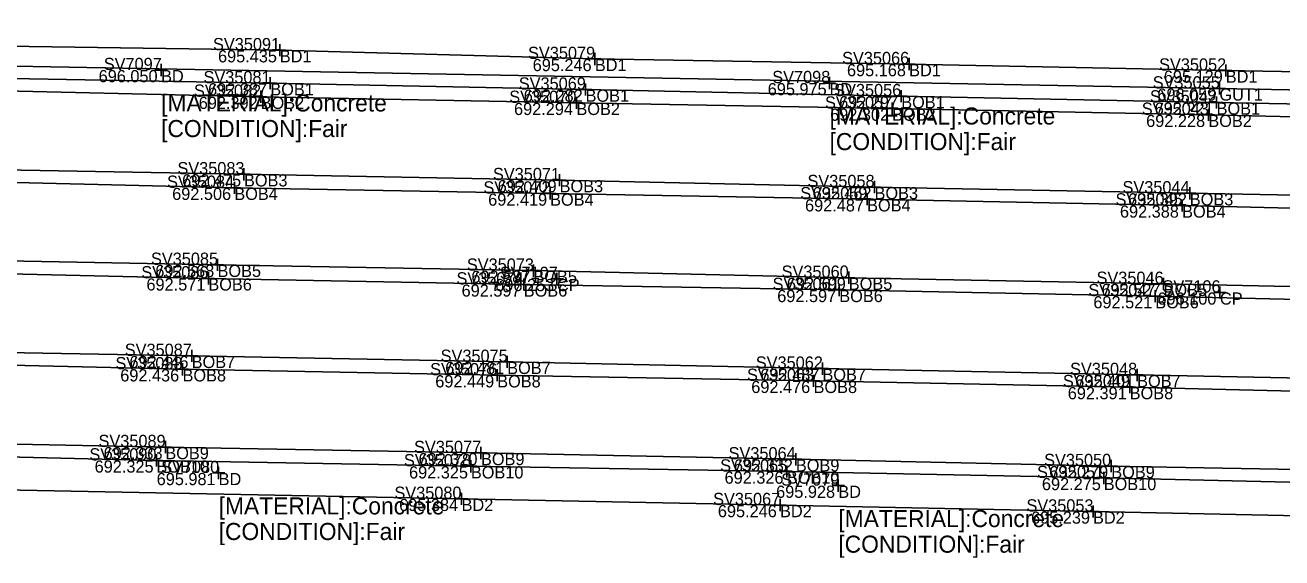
# Model space of a CAD drawing. Extents: x 1660019 to 1662995, y 619975 to 620342.
# Drawn here: x 1661348 to 1661451.1, y 620208.1 to 620251.8 of the extents above; entities that cross this region are included whole.
import ezdxf

# ---------------------------------------------------------------- set-up
doc = ezdxf.new("R2010")
doc.units = 0
for name, color, linetype in [('BR_X_Rail_Object', 7, 'Continuous'), ('BR_X_SV_Bottom_of_Beam', 7, 'Continuous'), ('BR_X_SV_Bottom_of_Beam_Text', 7, 'Continuous'), ('BR_X_SV_Deck_Top', 7, 'Continuous'), ('BR_X_SV_Deck_Top_Text', 7, 'Continuous'), ('PV_X_Curb', 7, 'Continuous'), ('RD_P_GR_Lt', 7, 'Continuous'), ('RD_X_GR_Bar', 7, 'Continuous'), ('RD_X_Wall', 7, 'Continuous'), ('SV_X_Text', 7, 'Continuous')]:
    doc.layers.add(name, color=color, linetype=linetype)

msp = doc.modelspace()

# ---------------------------------------------------------------- linework, layer by layer
at = {"layer": 'BR_X_SV_Bottom_of_Beam'}
for points in [[(1661523.4, 620243.85), (1661497.42, 620244.38), (1661471.69, 620244.95), (1661445.77, 620245.45), (1661419.9, 620245.97), (1661394.01, 620246.51), (1661368.15, 620247.03), (1661342.29, 620247.49), (1661316.31, 620248.04), (1661290.56, 620248.6), (1661264.65, 620249.03), (1661238.6, 620249.58)], [(1661517.58, 620243.01), (1661496.9, 620243.44), (1661470.92, 620243.84), (1661445.09, 620244.44), (1661419.15, 620244.95), (1661393.26, 620245.42), (1661367.36, 620245.92), (1661341.63, 620246.52), (1661315.65, 620247.11), (1661289.75, 620247.52), (1661264.38, 620248.32), (1661238.2, 620248.61)], [(1661521.26, 620236.36), (1661495.33, 620236.96), (1661469.49, 620237.51), (1661443.57, 620238), (1661417.71, 620238.51), (1661391.88, 620239.08), (1661365.99, 620239.56), (1661340.12, 620240.03), (1661314.2, 620240.59), (1661288.35, 620241.15), (1661262.48, 620241.61), (1661236.62, 620242.15)], [(1661520.6, 620235.45), (1661494.63, 620235.97), (1661468.71, 620236.38), (1661442.94, 620237), (1661417.1, 620237.51), (1661391.1, 620237.98), (1661365.2, 620238.45), (1661339.37, 620239.07), (1661313.5, 620239.59), (1661287.59, 620239.99), (1661261.72, 620240.63), (1661235.91, 620241.14)], [(1661519.08, 620228.95), (1661493.23, 620229.44), (1661467.37, 620230.03), (1661441.42, 620230.57), (1661415.6, 620231.07), (1661389.73, 620231.65), (1661363.82, 620232.13), (1661337.82, 620232.61), (1661311.99, 620233.08), (1661286.18, 620233.72), (1661260.33, 620234.13), (1661234.38, 620234.66)], [(1661518.51, 620227.98), (1661492.53, 620228.47), (1661466.56, 620228.95), (1661440.74, 620229.56), (1661414.82, 620230.07), (1661388.94, 620230.52), (1661363.07, 620231.02), (1661337.3, 620231.61), (1661311.53, 620232.16), (1661285.45, 620232.59), (1661259.59, 620233.14), (1661233.67, 620233.67)], [(1661516.94, 620221.49), (1661491.08, 620222.02), (1661465.19, 620222.58), (1661439.25, 620223.09), (1661413.44, 620223.61), (1661387.58, 620224.17), (1661361.7, 620224.66), (1661335.74, 620225.13), (1661309.88, 620225.69), (1661284.01, 620226.24), (1661258.16, 620226.7), (1661232.1, 620227.23)], [(1661516.25, 620220.54), (1661490.62, 620220.91), (1661464.53, 620221.45), (1661438.64, 620222.1), (1661412.71, 620222.61), (1661386.76, 620223.07), (1661360.95, 620223.56), (1661335.05, 620224.18), (1661309.21, 620224.72), (1661283.27, 620225.13), (1661257.54, 620225.69), (1661231.6, 620226.26)], [(1661514.76, 620214.06), (1661488.91, 620214.55), (1661463.02, 620215.15), (1661437.13, 620215.62), (1661411.26, 620216.17), (1661385.43, 620216.69), (1661359.54, 620217.18), (1661333.6, 620217.68), (1661307.75, 620218.18), (1661281.89, 620218.77), (1661255.86, 620219.28), (1661229.67, 620219.8)], [(1661514.07, 620213.08), (1661488.21, 620213.6), (1661462.26, 620214.04), (1661436.51, 620214.64), (1661410.52, 620215.17), (1661384.6, 620215.6), (1661358.81, 620216.08), (1661332.97, 620216.7), (1661307.11, 620217.25), (1661281.1, 620217.69), (1661255.32, 620218.27), (1661229.46, 620218.85)]]:
    msp.add_lwpolyline(points, dxfattribs=at)
at = {"layer": 'BR_X_SV_Deck_Top'}
for points in [[(1661524.15, 620246.52), (1661498.29, 620247.07), (1661472.43, 620247.6), (1661446.52, 620248.07), (1661420.55, 620248.6), (1661394.77, 620249.02), (1661368.93, 620249.74), (1661342.74, 620250.12), (1661316.87, 620250.71), (1661291.25, 620251.01), (1661265.13, 620251.8)], [(1661513.53, 620210.29), (1661487.66, 620211.1), (1661461.66, 620211.35), (1661435.63, 620211.89), (1661409.96, 620212.42), (1661383.84, 620212.93), (1661332.3, 620213.95), (1661306.25, 620214.44), (1661280.43, 620214.97), (1661254.73, 620215.77)]]:
    msp.add_lwpolyline(points, dxfattribs=at)
at = {"layer": 'PV_X_Curb'}
msp.add_lwpolyline([(1661523.34, 620245.12), (1661471.57, 620246.11), (1661446, 620246.6), (1661316.22, 620249.01), (1661290.79, 620249.44), (1661264.95, 620250.25), (1661238.71, 620250.79)], dxfattribs=at)
at = {"layer": 'RD_P_GR_Lt'}
for p, q in [((1661368.43, 620249.74), (1661369.43, 620249.74)), ((1661368.93, 620250.24), (1661368.93, 620249.24)), ((1661368.93, 620249.74), (1661368.93, 620249.74)), ((1661394.77, 620249.52), (1661394.77, 620248.52)), ((1661359.19, 620248.61), (1661359.19, 620247.61)), ((1661394.27, 620249.02), (1661395.27, 620249.02)), ((1661394.77, 620249.02), (1661394.77, 620249.02)), ((1661420.05, 620248.6), (1661421.05, 620248.6)), ((1661420.55, 620249.1), (1661420.55, 620248.1)), ((1661420.55, 620248.6), (1661420.55, 620248.6)), ((1661446.52, 620248.57), (1661446.52, 620247.57)), ((1661358.69, 620248.11), (1661359.69, 620248.11)), ((1661359.19, 620248.11), (1661359.19, 620248.11)), ((1661368.15, 620247.53), (1661368.15, 620246.53)), ((1661414.02, 620247.54), (1661414.02, 620246.54)), ((1661446.02, 620248.07), (1661447.02, 620248.07)), ((1661446.52, 620248.07), (1661446.52, 620248.07)), ((1661367.36, 620246.42), (1661367.36, 620245.42)), ((1661367.65, 620247.03), (1661368.65, 620247.03)), ((1661368.15, 620247.03), (1661368.15, 620247.03)), ((1661393.51, 620246.51), (1661394.51, 620246.51)), ((1661394.01, 620247.01), (1661394.01, 620246.01)), ((1661394.01, 620246.51), (1661394.01, 620246.51)), ((1661413.52, 620247.04), (1661414.52, 620247.04)), ((1661414.02, 620247.04), (1661414.02, 620247.04)), ((1661419.9, 620246.47), (1661419.9, 620245.47)), ((1661445.5, 620246.6), (1661446.5, 620246.6)), ((1661446, 620247.1), (1661446, 620246.1)), ((1661446, 620246.6), (1661446, 620246.6)), ((1661366.86, 620245.92), (1661367.86, 620245.92)), ((1661367.36, 620245.92), (1661367.36, 620245.92)), ((1661392.76, 620245.42), (1661393.76, 620245.42)), ((1661393.26, 620245.92), (1661393.26, 620244.92)), ((1661393.26, 620245.42), (1661393.26, 620245.42)), ((1661419.15, 620245.45), (1661419.15, 620244.45)), ((1661419.4, 620245.97), (1661420.4, 620245.97)), ((1661419.9, 620245.97), (1661419.9, 620245.97)), ((1661445.27, 620245.45), (1661446.27, 620245.45)), ((1661445.77, 620245.95), (1661445.77, 620244.95)), ((1661445.77, 620245.45), (1661445.77, 620245.45)), ((1661418.65, 620244.95), (1661419.65, 620244.95)), ((1661419.15, 620244.95), (1661419.15, 620244.95)), ((1661444.59, 620244.44), (1661445.59, 620244.44)), ((1661445.09, 620244.94), (1661445.09, 620243.94)), ((1661445.09, 620244.44), (1661445.09, 620244.44)), ((1661365.49, 620239.56), (1661366.49, 620239.56)), ((1661365.99, 620240.06), (1661365.99, 620239.06)), ((1661365.99, 620239.56), (1661365.99, 620239.56)), ((1661391.88, 620239.58), (1661391.88, 620238.58)), ((1661364.7, 620238.45), (1661365.7, 620238.45)), ((1661365.2, 620238.95), (1661365.2, 620237.95)), ((1661365.2, 620238.45), (1661365.2, 620238.45)), ((1661391.1, 620238.48), (1661391.1, 620237.48)), ((1661391.38, 620239.08), (1661392.38, 620239.08)), ((1661391.88, 620239.08), (1661391.88, 620239.08)), ((1661417.21, 620238.51), (1661418.21, 620238.51)), ((1661417.71, 620239.01), (1661417.71, 620238.01)), ((1661417.71, 620238.51), (1661417.71, 620238.51)), ((1661443.57, 620238.5), (1661443.57, 620237.5)), ((1661390.6, 620237.98), (1661391.6, 620237.98)), ((1661391.1, 620237.98), (1661391.1, 620237.98)), ((1661416.6, 620237.51), (1661417.6, 620237.51)), ((1661417.1, 620238.01), (1661417.1, 620237.01)), ((1661417.1, 620237.51), (1661417.1, 620237.51)), ((1661442.94, 620237.5), (1661442.94, 620236.5)), ((1661443.07, 620238), (1661444.07, 620238)), ((1661443.57, 620238), (1661443.57, 620238)), ((1661442.44, 620237), (1661443.44, 620237)), ((1661442.94, 620237), (1661442.94, 620237)), ((1661363.32, 620232.13), (1661364.32, 620232.13)), ((1661363.82, 620232.63), (1661363.82, 620231.63)), ((1661363.82, 620232.13), (1661363.82, 620232.13)), ((1661389.73, 620232.15), (1661389.73, 620231.15)), ((1661362.57, 620231.02), (1661363.57, 620231.02)), ((1661363.07, 620231.52), (1661363.07, 620230.52)), ((1661363.07, 620231.02), (1661363.07, 620231.02)), ((1661388.94, 620231.02), (1661388.94, 620230.02)), ((1661389.23, 620231.65), (1661390.23, 620231.65)), ((1661389.73, 620231.65), (1661389.73, 620231.65)), ((1661391.16, 620230.97), (1661392.16, 620230.97)), ((1661391.66, 620231.47), (1661391.66, 620230.47)), ((1661391.66, 620230.97), (1661391.66, 620230.97)), ((1661415.1, 620231.07), (1661416.1, 620231.07)), ((1661415.6, 620231.57), (1661415.6, 620230.57)), ((1661415.6, 620231.07), (1661415.6, 620231.07)), ((1661441.42, 620231.07), (1661441.42, 620230.07)), ((1661388.44, 620230.52), (1661389.44, 620230.52)), ((1661388.94, 620230.52), (1661388.94, 620230.52)), ((1661414.32, 620230.07), (1661415.32, 620230.07)), ((1661414.82, 620230.57), (1661414.82, 620229.57)), ((1661414.82, 620230.07), (1661414.82, 620230.07)), ((1661440.74, 620230.06), (1661440.74, 620229.06)), ((1661440.92, 620230.57), (1661441.92, 620230.57)), ((1661441.42, 620230.57), (1661441.42, 620230.57)), ((1661446.04, 620230.36), (1661446.04, 620229.36)), ((1661440.24, 620229.56), (1661441.24, 620229.56)), ((1661440.74, 620229.56), (1661440.74, 620229.56)), ((1661445.54, 620229.86), (1661446.54, 620229.86)), ((1661446.04, 620229.86), (1661446.04, 620229.86)), ((1661361.7, 620225.16), (1661361.7, 620224.16)), ((1661360.95, 620224.06), (1661360.95, 620223.06)), ((1661361.2, 620224.66), (1661362.2, 620224.66)), ((1661361.7, 620224.66), (1661361.7, 620224.66)), ((1661387.08, 620224.17), (1661388.08, 620224.17)), ((1661387.58, 620224.67), (1661387.58, 620223.67)), ((1661387.58, 620224.17), (1661387.58, 620224.17)), ((1661413.44, 620224.11), (1661413.44, 620223.11)), ((1661360.45, 620223.56), (1661361.45, 620223.56)), ((1661360.95, 620223.56), (1661360.95, 620223.56)), ((1661386.26, 620223.07), (1661387.26, 620223.07)), ((1661386.76, 620223.57), (1661386.76, 620222.57)), ((1661386.76, 620223.07), (1661386.76, 620223.07)), ((1661412.71, 620223.11), (1661412.71, 620222.11)), ((1661412.94, 620223.61), (1661413.94, 620223.61)), ((1661413.44, 620223.61), (1661413.44, 620223.61)), ((1661438.75, 620223.09), (1661439.75, 620223.09)), ((1661439.25, 620223.59), (1661439.25, 620222.59)), ((1661439.25, 620223.09), (1661439.25, 620223.09)), ((1661412.21, 620222.61), (1661413.21, 620222.61)), ((1661412.71, 620222.61), (1661412.71, 620222.61)), ((1661438.14, 620222.1), (1661439.14, 620222.1)), ((1661438.64, 620222.6), (1661438.64, 620221.6)), ((1661438.64, 620222.1), (1661438.64, 620222.1)), ((1661359.54, 620217.68), (1661359.54, 620216.68)), ((1661358.81, 620216.58), (1661358.81, 620215.58)), ((1661359.04, 620217.18), (1661360.04, 620217.18)), ((1661359.54, 620217.18), (1661359.54, 620217.18)), ((1661384.93, 620216.69), (1661385.93, 620216.69)), ((1661385.43, 620217.19), (1661385.43, 620216.19)), ((1661385.43, 620216.69), (1661385.43, 620216.69)), ((1661411.26, 620216.67), (1661411.26, 620215.67)), ((1661358.31, 620216.08), (1661359.31, 620216.08)), ((1661358.81, 620216.08), (1661358.81, 620216.08)), ((1661363.91, 620215.55), (1661363.91, 620214.55)), ((1661384.1, 620215.6), (1661385.1, 620215.6)), ((1661384.6, 620216.1), (1661384.6, 620215.1)), ((1661384.6, 620215.6), (1661384.6, 620215.6)), ((1661410.52, 620215.67), (1661410.52, 620214.67)), ((1661410.76, 620216.17), (1661411.76, 620216.17)), ((1661411.26, 620216.17), (1661411.26, 620216.17)), ((1661436.63, 620215.62), (1661437.63, 620215.62)), ((1661437.13, 620216.12), (1661437.13, 620215.12)), ((1661437.13, 620215.62), (1661437.13, 620215.62)), ((1661363.41, 620215.05), (1661364.41, 620215.05)), ((1661363.91, 620215.05), (1661363.91, 620215.05)), ((1661410.02, 620215.17), (1661411.02, 620215.17)), ((1661410.52, 620215.17), (1661410.52, 620215.17)), ((1661414.74, 620214.51), (1661414.74, 620213.51)), ((1661436.01, 620214.64), (1661437.01, 620214.64)), ((1661436.51, 620215.14), (1661436.51, 620214.14)), ((1661436.51, 620214.64), (1661436.51, 620214.64)), ((1661383.84, 620213.43), (1661383.84, 620212.43)), ((1661414.24, 620214.01), (1661415.24, 620214.01)), ((1661414.74, 620214.01), (1661414.74, 620214.01)), ((1661383.34, 620212.93), (1661384.34, 620212.93)), ((1661383.84, 620212.93), (1661383.84, 620212.93)), ((1661409.46, 620212.42), (1661410.46, 620212.42)), ((1661409.96, 620212.92), (1661409.96, 620211.92)), ((1661409.96, 620212.42), (1661409.96, 620212.42)), ((1661435.63, 620212.39), (1661435.63, 620211.39)), ((1661435.13, 620211.89), (1661436.13, 620211.89)), ((1661435.63, 620211.89), (1661435.63, 620211.89))]:
    msp.add_line(p, q, dxfattribs=at)

# ---------------------------------------------------------------- texts
at = {"layer": 'BR_X_Rail_Object'}
for s, p in [('GUT1', (1661446, 620245.6)), ('CP', (1661391.66, 620229.97)), ('CP', (1661446.04, 620228.86))]:
    msp.add_text(s, height=1, dxfattribs=at).set_placement(p)
at = {"layer": 'BR_X_SV_Bottom_of_Beam_Text'}
for s, p in [('SV35081', (1661362.67, 620247.03)), ('SV35069', (1661388.53, 620246.51)), ('SV35082', (1661361.89, 620245.92)), ('692.387', (1661363.05, 620246.03)), ('BOB1', (1661368.15, 620246.03)), ('SV35070', (1661387.75, 620245.42)), ('692.282', (1661388.94, 620245.51)), ('BOB1', (1661394.01, 620245.51)), ('SV35056', (1661414.4, 620245.97)), ('SV35042', (1661440.3, 620245.45)), ('692.392', (1661362.28, 620244.92)), ('BOB2', (1661367.36, 620244.92)), ('692.294', (1661388.14, 620244.42)), ('BOB2', (1661393.26, 620244.42)), ('SV35057', (1661413.65, 620244.95)), ('692.297', (1661414.81, 620244.97)), ('BOB1', (1661419.9, 620244.97)), ('SV35043', (1661439.63, 620244.44)), ('692.221', (1661440.69, 620244.45)), ('BOB1', (1661445.77, 620244.45)), ('692.302', (1661414.07, 620243.95)), ('BOB2', (1661419.15, 620243.95)), ('692.228', (1661439.99, 620243.44)), ('BOB2', (1661445.09, 620243.44)), ('SV35083', (1661360.53, 620239.56)), ('SV35084', (1661359.68, 620238.45)), ('692.475', (1661360.92, 620238.56)), ('BOB3', (1661365.99, 620238.56)), ('SV35071', (1661386.41, 620239.08)), ('SV35058', (1661412.21, 620238.51)), ('692.506', (1661360.1, 620237.45)), ('BOB4', (1661365.2, 620237.45)), ('SV35072', (1661385.63, 620237.98)), ('692.409', (1661386.8, 620238.08)), ('BOB3', (1661391.88, 620238.08)), ('SV35059', (1661411.62, 620237.51)), ('692.462', (1661412.63, 620237.51)), ('BOB3', (1661417.71, 620237.51)), ('SV35044', (1661438.05, 620238)), ('692.419', (1661386.02, 620236.98)), ('BOB4', (1661391.1, 620236.98)), ('692.487', (1661412.01, 620236.51)), ('BOB4', (1661417.1, 620236.51)), ('SV35045', (1661437.48, 620237)), ('692.392', (1661438.5, 620237)), ('BOB3', (1661443.57, 620237)), ('692.388', (1661437.84, 620236)), ('BOB4', (1661442.94, 620236)), ('SV35085', (1661358.36, 620232.13)), ('SV35086', (1661357.57, 620231.02)), ('692.568', (1661358.72, 620231.13)), ('BOB5', (1661363.82, 620231.13)), ('SV35073', (1661384.27, 620231.65)), ('SV35060', (1661410.09, 620231.07)), ('692.571', (1661357.99, 620230.02)), ('BOB6', (1661363.07, 620230.02)), ('SV35074', (1661383.42, 620230.52)), ('692.587', (1661384.64, 620230.65)), ('BOB5', (1661389.73, 620230.65)), ('SV35061', (1661409.35, 620230.07)), ('692.599', (1661410.52, 620230.07)), ('BOB5', (1661415.6, 620230.07)), ('SV35046', (1661435.92, 620230.57)), ('692.597', (1661383.84, 620229.52)), ('BOB6', (1661388.94, 620229.52)), ('692.597', (1661409.73, 620229.07)), ('BOB6', (1661414.82, 620229.07)), ('SV35047', (1661435.25, 620229.56)), ('692.527', (1661436.33, 620229.57)), ('BOB5', (1661441.42, 620229.57)), ('692.521', (1661435.66, 620228.56)), ('BOB6', (1661440.74, 620228.56)), ('SV35087', (1661356.21, 620224.66)), ('SV35075', (1661382.12, 620224.17)), ('SV35088', (1661355.45, 620223.56)), ('692.446', (1661356.6, 620223.66)), ('BOB7', (1661361.7, 620223.66)), ('SV35076', (1661381.26, 620223.07)), ('692.481', (1661382.5, 620223.17)), ('BOB7', (1661387.58, 620223.17)), ('SV35062', (1661407.97, 620223.61)), ('SV35048', (1661433.75, 620223.09)), ('692.436', (1661355.84, 620222.56)), ('BOB8', (1661360.95, 620222.56)), ('692.449', (1661381.68, 620222.07)), ('BOB8', (1661386.76, 620222.07)), ('SV35063', (1661407.25, 620222.61)), ('692.487', (1661408.35, 620222.61)), ('BOB7', (1661413.44, 620222.61)), ('SV35049', (1661433.16, 620222.1)), ('692.401', (1661434.17, 620222.09)), ('BOB7', (1661439.25, 620222.09)), ('692.476', (1661407.6, 620221.61)), ('BOB8', (1661412.71, 620221.61)), ('692.391', (1661433.56, 620221.1)), ('BOB8', (1661438.64, 620221.1)), ('SV35089', (1661354.06, 620217.18)), ('SV35077', (1661379.94, 620216.69)), ('SV35090', (1661353.31, 620216.08)), ('692.333', (1661354.48, 620216.18)), ('BOB9', (1661359.54, 620216.18)), ('SV35078', (1661379.11, 620215.6)), ('692.320', (1661380.31, 620215.69)), ('BOB9', (1661385.43, 620215.69)), ('SV35064', (1661405.74, 620216.17)), ('SV35050', (1661431.62, 620215.62)), ('692.325', (1661353.74, 620215.08)), ('BOB10', (1661358.81, 620215.08)), ('692.325', (1661379.53, 620214.6)), ('BOB10', (1661384.6, 620214.6)), ('SV35065', (1661405.05, 620215.17)), ('692.332', (1661406.18, 620215.17)), ('BOB9', (1661411.26, 620215.17)), ('SV35051', (1661431.04, 620214.64)), ('692.279', (1661432.04, 620214.62)), ('BOB9', (1661437.13, 620214.62)), ('692.326', (1661405.41, 620214.17)), ('BOB10', (1661410.52, 620214.17)), ('692.275', (1661431.44, 620213.64)), ('BOB10', (1661436.51, 620213.64))]:
    msp.add_text(s, height=1, dxfattribs=at).set_placement(p)
at = {"layer": 'BR_X_SV_Deck_Top_Text'}
for s, p in [('SV35091', (1661363.45, 620249.74)), ('695.435', (1661363.86, 620248.74)), ('BD1', (1661368.93, 620248.74)), ('SV35079', (1661389.29, 620249.02)), ('SV35066', (1661415.05, 620248.6)), ('SV7097', (1661354.49, 620248.11)), ('695.246', (1661389.67, 620248.02)), ('BD1', (1661394.77, 620248.02)), ('695.168', (1661415.45, 620247.6)), ('BD1', (1661420.55, 620247.6)), ('SV35052', (1661441.05, 620248.07)), ('696.050', (1661354.07, 620247.11)), ('BD', (1661359.19, 620247.11)), ('SV7098', (1661409.32, 620247.04)), ('695.129', (1661441.44, 620247.07)), ('BD1', (1661446.52, 620247.07)), ('695.975', (1661408.95, 620246.04)), ('BD', (1661414.02, 620246.04)), ('SV7080', (1661359.2, 620215.05)), ('695.981', (1661358.83, 620214.05)), ('BD', (1661363.91, 620214.05)), ('SV7079', (1661410.06, 620214.01)), ('SV35080', (1661378.33, 620212.93)), ('SV35067', (1661404.47, 620212.42)), ('695.928', (1661409.64, 620213.01)), ('BD', (1661414.74, 620213.01)), ('695.384', (1661378.72, 620211.93)), ('BD2', (1661383.84, 620211.93)), ('695.246', (1661404.86, 620211.42)), ('BD2', (1661409.96, 620211.42)), ('SV35053', (1661430.17, 620211.89)), ('695.239', (1661430.55, 620210.89)), ('BD2', (1661435.63, 620210.89))]:
    msp.add_text(s, height=1, dxfattribs=at).set_placement(p)
at = {"layer": 'RD_X_GR_Bar'}
for s, p in [('696.059', (1661440.91, 620245.6)), ('696.253', (1661386.6, 620229.97)), ('696.100', (1661440.92, 620228.86))]:
    msp.add_text(s, height=1, dxfattribs=at).set_placement(p)
at = {"layer": 'RD_X_Wall'}
for s, p in [('SV35055', (1661440.53, 620246.6)), ('SV7107', (1661386.97, 620230.97)), ('SV7106', (1661441.33, 620229.86))]:
    msp.add_text(s, height=1, dxfattribs=at).set_placement(p)
at = {"layer": 'SV_X_Text'}
for s, p in [('[MATERIAL]:Concrete', (1661359.19, 620244.71)), ('[MATERIAL]:Concrete', (1661414.02, 620243.64)), ('[CONDITION]:Fair', (1661359.19, 620242.61)), ('[CONDITION]:Fair', (1661414.02, 620241.54)), ('[MATERIAL]:Concrete', (1661363.91, 620211.65)), ('[MATERIAL]:Concrete', (1661414.74, 620210.61)), ('[CONDITION]:Fair', (1661363.91, 620209.55)), ('[CONDITION]:Fair', (1661414.74, 620208.51))]:
    msp.add_text(s, height=1.4, dxfattribs=at).set_placement(p)

doc.saveas('drawing.dxf')
